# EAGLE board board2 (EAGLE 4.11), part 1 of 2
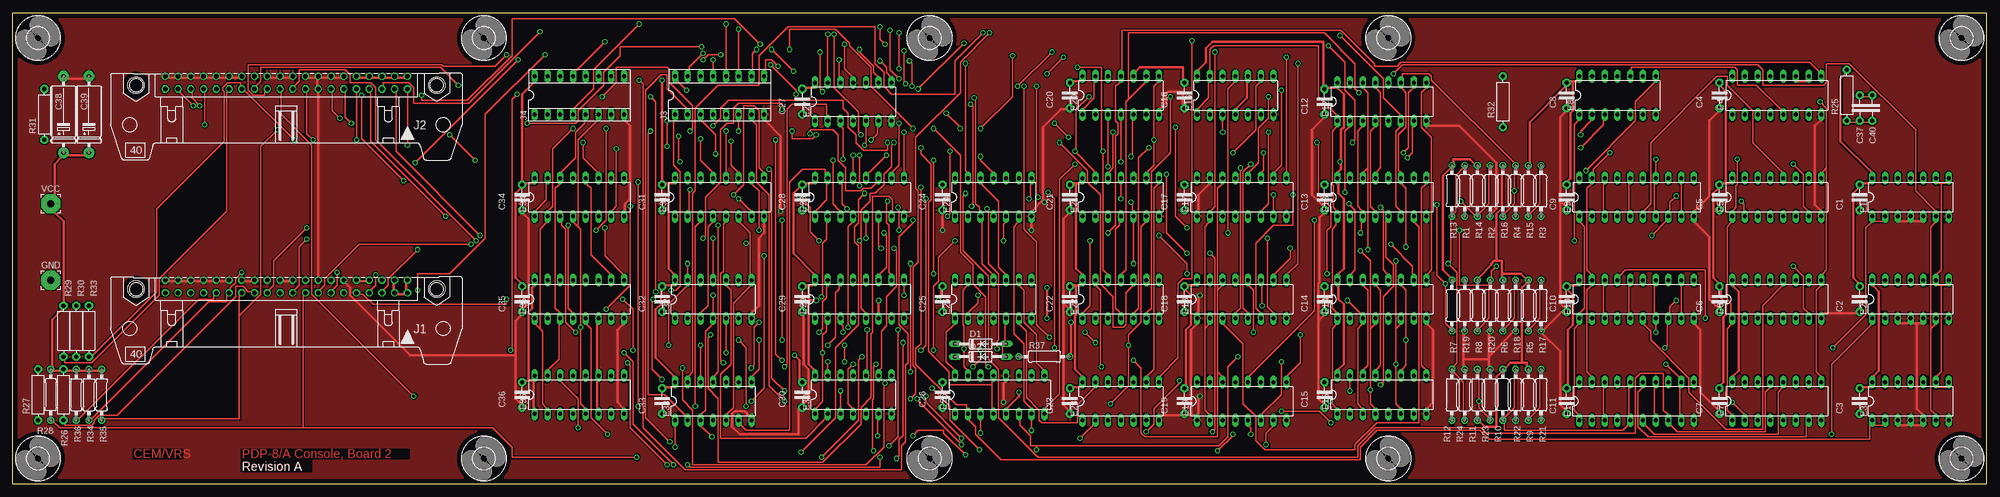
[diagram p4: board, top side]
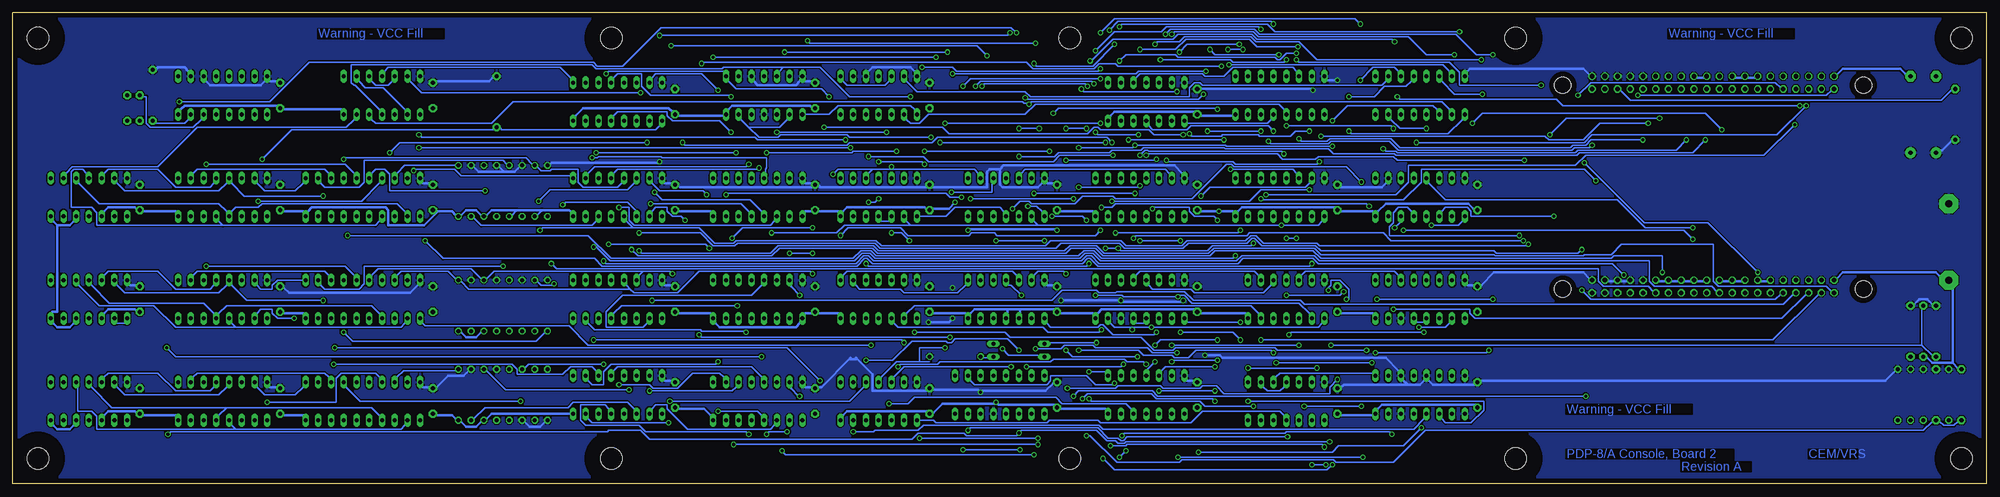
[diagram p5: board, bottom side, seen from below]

Size 393.7 x 93.98 mm. Coordinates in mm from the lower left corner, seen from the top.
Outline: 0,0 0,93.98 393.7,93.98 393.7,0 0,0
Copper layers (1*16): Top 0.035mm / dielectric 1.5mm / Bottom 0.035mm
Design rules "olimex8mil": minimum track width 10mil, minimum drill 24mil, track to track 8mil, track to pad 8mil, pad to pad 10mil, via to via 8mil, smd to smd 8mil, copper to edge 40mil, drill to drill 10mil, minimum pad ring 10mil, minimum via ring 8mil, stop-mask expansion 0mil, vias tented up to drill 0mil, thermal gap 10mil
Net classes: 1 Supply: width 0.508 mm

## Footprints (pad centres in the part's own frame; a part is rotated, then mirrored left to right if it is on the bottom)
C-5 = drill 0.813 pad 1.6 octagon: 1 -2.54,0; 2 2.54,0
E15-5 = drill 0.813 pad 2.159 round: + -7.62,0 | drill 0.813 pad 2.159 octagon: - 7.62,0
DO35-10 = drill 0.813 long: A 5.08,0; C -5.08,0
DIL14 = drill 0.813 long: 1 -7.62,-3.81; 2 -5.08,-3.81; 3 -2.54,-3.81; 4 0,-3.81; 5 2.54,-3.81; 6 5.08,-3.81; 7 7.62,-3.81; 8 7.62,3.81; 9 5.08,3.81; 10 2.54,3.81; 11 0,3.81; 12 -2.54,3.81; 13 -5.08,3.81; 14 -7.62,3.81
DIL16 = drill 0.813 long: 1 -8.89,-3.81; 2 -6.35,-3.81; 3 -3.81,-3.81; 4 -1.27,-3.81; 5 1.27,-3.81; 6 3.81,-3.81; 7 6.35,-3.81; 8 8.89,-3.81; 9 8.89,3.81; 10 6.35,3.81; 11 3.81,3.81; 12 1.27,3.81; 13 -1.27,3.81; 14 -3.81,3.81; 15 -6.35,3.81; 16 -8.89,3.81
DIL20 = drill 0.813 long: 1 -11.43,-3.81; 2 -8.89,-3.81; 3 -6.35,-3.81; 4 -3.81,-3.81; 5 -1.27,-3.81; 6 1.27,-3.81; 7 3.81,-3.81; 8 6.35,-3.81; 9 8.89,-3.81; 10 11.43,-3.81; 11 11.43,3.81; 12 8.89,3.81; 13 6.35,3.81; 14 3.81,3.81; 15 1.27,3.81; 16 -1.27,3.81; 17 -3.81,3.81; 18 -6.35,3.81; 19 -8.89,3.81; 20 -11.43,3.81
3,81/1,4 = drill 1.397 pad 3.81 octagon: 1 0,0
40H = drill 0.914 round: 1 -24.13,-1.27 | drill 0.914 octagon: 2 -24.13,1.27; 3 -21.59,-1.27; 4 -21.59,1.27; 5 -19.05,-1.27; 6 -19.05,1.27; 7 -16.51,-1.27; 8 -16.51,1.27; 9 -13.97,-1.27; 10 -13.97,1.27; 11 -11.43,-1.27; 12 -11.43,1.27; 13 -8.89,-1.27; 14 -8.89,1.27; 15 -6.35,-1.27; 16 -6.35,1.27; 17 -3.81,-1.27; 18 -3.81,1.27; 19 -1.27,-1.27; 20 -1.27,1.27; 21 1.27,-1.27; 22 1.27,1.27; 23 3.81,-1.27; 24 3.81,1.27; 25 6.35,-1.27; 26 6.35,1.27; 27 8.89,-1.27; 28 8.89,1.27; 29 11.43,-1.27; 30 11.43,1.27; 31 13.97,-1.27; 32 13.97,1.27; 33 16.51,-1.27; 34 16.51,1.27; 35 19.05,-1.27; 36 19.05,1.27; 37 21.59,-1.27; 38 21.59,1.27; 39 24.13,-1.27; 40 24.13,1.27 | hole 3.302: -29.972,0.533; 29.972,0.533
SOCKED-16 = drill 0.813 long: 1 -8.89,-3.81; 2 -6.35,-3.81; 3 -3.81,-3.81; 4 -1.27,-3.81; 5 1.27,-3.81; 6 3.81,-3.81; 7 6.35,-3.81; 8 8.89,-3.81; 9 8.89,3.81; 10 6.35,3.81; 11 3.81,3.81; 12 1.27,3.81; 13 -1.27,3.81; 14 -3.81,3.81; 15 -6.35,3.81; 16 -8.89,3.81
0207/10 = drill 0.813 octagon: 1 -5.08,0; 2 5.08,0
R-10 = drill 0.813 pad 1.6 octagon: 1 -5.08,0; 2 5.08,0
4,3 = hole 4.3: 0,0

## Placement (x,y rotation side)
C1  [C-5]  368.3,57.15 90 top
C2  [C-5]  368.3,36.83 90 top
C3  [C-5]  368.3,16.51 90 top
C4  [C-5]  340.36,77.47 90 top
C5  [C-5]  340.36,57.15 90 top
C6  [C-5]  340.36,36.83 90 top
C7  [C-5]  340.36,16.51 90 top
C8  [C-5]  309.88,77.47 90 top
C9  [C-5]  309.88,57.15 90 top
C10  [C-5]  309.88,36.83 90 top
C11  [C-5]  309.88,16.51 90 top
C12  [C-5]  261.62,76.2 90 top
C13  [C-5]  261.62,57.15 90 top
C14  [C-5]  261.62,36.83 90 top
C15  [C-5]  261.62,17.78 90 top
C16  [C-5]  233.68,77.47 90 top
C17  [C-5]  233.68,57.15 90 top
C18  [C-5]  233.68,36.83 90 top
C19  [C-5]  233.68,16.51 90 top
C20  [C-5]  210.82,77.47 90 top
C21  [C-5]  210.82,57.15 90 top
C22  [C-5]  210.82,36.83 90 top
C23  [C-5]  210.82,16.51 90 top
C24  [C-5]  185.42,57.15 90 top
C25  [C-5]  185.42,36.83 90 top
C26  [C-5]  185.42,17.78 90 top
C27  [C-5]  157.48,76.2 90 top
C28  [C-5]  157.48,57.15 90 top
C29  [C-5]  157.48,36.83 90 top
C30  [C-5]  157.48,17.78 90 top
C31  [C-5]  129.54,57.15 90 top
C32  [C-5]  129.54,36.83 90 top
C33  [C-5]  129.54,16.51 90 top
C34  [C-5]  101.6,57.15 90 top
C35  [C-5]  101.6,36.83 90 top
C36  [C-5]  101.6,17.78 90 top
C37  10  [C-5]  368.3,74.93 270 top
C38  6.8uf  [E15-5]  10.16,73.66 90 top
C39  6.8uf  [E15-5]  15.24,73.66 90 top
C40  47  [C-5]  370.84,74.93 270 top
D1  1N4148  [DO35-10]  193.04,27.94 0 top
D2  1N4148  [DO35-10]  193.04,25.4 0 top
E1  74LS95N  [DIL14]  378.46,57.15 0 top
E2  74LS95N  [DIL14]  378.46,36.83 0 top
E3  74LS95N  [DIL14]  378.46,16.51 0 top
E4  74LS123N  [DIL16]  351.79,77.47 0 top
E5  74LS175N  [DIL16]  351.79,57.15 0 top
E6  74LS175N  [DIL16]  351.79,36.83 0 top
E7  74LS175N  [DIL16]  351.79,16.51 0 top
E8  74LS00N  [DIL14]  320.04,77.47 0 top
E9  74S244N  [DIL20]  323.85,57.15 0 top
E10  74S244N  [DIL20]  323.85,36.83 0 top
E11  74S244N  [DIL20]  323.85,16.51 0 top
E12  74LS174N  [DIL16]  273.05,76.2 0 top
E13  74LS174N  [DIL16]  273.05,57.15 0 top
E14  74LS174N  [DIL16]  273.05,36.83 0 top
E15  74LS174N  [DIL16]  273.05,17.78 0 top
E16  74LS74N  [DIL14]  243.84,77.47 0 top
E17  74LS153N  [DIL16]  245.11,57.15 0 top
E18  74LS153N  [DIL16]  245.11,36.83 0 top
E19  74LS153N  [DIL16]  245.11,16.51 0 top
E20  74LS74N  [DIL14]  220.98,77.47 0 top
E21  74LS27N  [DIL14]  220.98,57.15 0 top
E22  74LS02N  [DIL14]  220.98,36.83 0 top
E23  7416N  [DIL14]  220.98,16.51 0 top
E24  74LS04N  [DIL14]  195.58,57.15 0 top
E25  74LS27N  [DIL14]  195.58,36.83 0 top
E26  74LS75N  [DIL16]  196.85,17.78 0 top
E27  7404N  [DIL14]  167.64,76.2 0 top
E28  74LS367N  [DIL16]  168.91,57.15 0 top
E29  74LS138N  [DIL16]  168.91,36.83 0 top
E30  74LS00N  [DIL14]  167.64,17.78 0 top
E31  74LS367N  [DIL16]  140.97,57.15 0 top
E32  74LS08N  [DIL14]  139.7,36.83 0 top
E33  74LS02N  [DIL14]  139.7,16.51 0 top
E34  74LS367N  [DIL16]  113.03,57.15 0 top
E35  74LS138N  [DIL16]  113.03,36.83 0 top
E36  74LS174N  [DIL16]  113.03,17.78 0 top
GND  [3,81/1,4]  7.62,40.64 0 top
J1  [40H]  54.61,39.37 180 top
J2  [40H]  54.61,80.01 180 top
J3  [SOCKED-16]  140.97,77.47 0 top
J4  [SOCKED-16]  113.03,77.47 0 top
R1  680  [0207/10]  289.56,58.42 90 top
R2  680  [0207/10]  294.64,58.42 90 top
R3  680  [0207/10]  304.8,58.42 90 top
R4  680  [0207/10]  299.72,58.42 90 top
R5  330  [0207/10]  302.26,35.56 90 top
R6  330  [0207/10]  297.18,35.56 90 top
R7  330  [0207/10]  287.02,35.56 90 top
R8  330  [0207/10]  292.1,35.56 90 top
R9  330  [0207/10]  302.26,17.78 90 top
R10  330  [0207/10]  297.18,17.78 90 top
R11  330  [0207/10]  292.1,17.78 270 top
R12  330  [0207/10]  287.02,17.78 270 top
R13  330  [0207/10]  287.02,58.42 90 top
R14  330  [0207/10]  292.1,58.42 90 top
R15  330  [0207/10]  302.26,58.42 90 top
R16  330  [0207/10]  297.18,58.42 90 top
R17  680  [0207/10]  304.8,35.56 90 top
R18  680  [0207/10]  299.72,35.56 90 top
R19  680  [0207/10]  289.56,35.56 90 top
R20  680  [0207/10]  294.64,35.56 90 top
R21  680  [0207/10]  304.8,17.78 90 top
R22  680  [0207/10]  299.72,17.78 90 top
R23  680  [0207/10]  294.64,17.78 270 top
R24  680  [0207/10]  289.56,17.78 270 top
R25  6K8  [R-10]  365.76,77.47 90 top
R26  180  [R-10]  10.16,17.78 270 top
R27  390  [R-10]  5.08,17.78 90 top
R28  1K  [0207/10]  7.62,17.78 90 top
R29  180  [R-10]  10.16,30.48 270 top
R30  390  [R-10]  12.7,30.48 270 top
R31  1K  [R-10]  6.35,73.66 90 top
R32  1K  [R-10]  297.18,76.2 270 top
R33  1K  [R-10]  15.24,30.48 270 top
R34  1K  [0207/10]  15.24,17.78 270 top
R35  1K  [0207/10]  17.78,17.78 270 top
R36  1K  [0207/10]  12.7,17.78 270 top
R37  10K  [0207/10]  205.74,25.4 0 top
U$11  [4,3]  93.98,88.9 0 top
U$12  [4,3]  5.08,88.9 0 top
U$13  [4,3]  182.88,88.9 0 top
U$14  [4,3]  274.32,88.9 0 top
U$15  [4,3]  388.62,88.9 0 top
U$16  [4,3]  388.62,5.08 0 top
U$17  [4,3]  274.32,5.08 0 top
U$18  [4,3]  182.88,5.08 0 top
U$19  [4,3]  93.98,5.08 0 top
U$20  [4,3]  5.08,5.08 0 top
VCC  [3,81/1,4]  7.62,55.88 0 top

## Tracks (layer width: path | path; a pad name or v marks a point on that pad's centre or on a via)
ADDR0  (via drill 0.61)
  Top 0.254: v256.29,83.82 256.29,43.94 254.25,41.91 E18.9 | v152.65,83.31 151.38,84.58 150.11,84.58 150.11,82.55 J3.9
  Bottom 0.254: v256.29,83.82 256.03,84.07 191.52,84.07 190.25,82.8 178.05,82.8 177.04,83.82 173.74,83.82 173.23,83.31 v152.65,83.31
ADDR1  (via drill 0.61)
  Top 0.254: v251.46,57.66 251.46,54.61 E17.7 | v204.47,57.15 204.22,57.4 v204.22,79.25 | v176.78,80.77 175.01,82.55 v175.01,90.42 | v142.24,91.69 142.24,82.55 J3.12
  Bottom 0.254: v251.46,57.66 251.21,57.91 207.52,57.91 206.76,57.15 v204.47,57.15 | v204.22,79.25 202.69,80.77 v176.78,80.77 | v175.01,90.42 173.23,92.2 142.75,92.2 v142.24,91.69
ADDR2  (via drill 0.61)
  Top 0.254: v254,85.09 254,62.23 E17.9 | v206.25,81.79 v209.55,85.09 | v155.7,82.3 v151.38,86.61 | v148.34,86.61 147.57,85.85 147.57,82.55 J3.10
  Bottom 0.254: v209.55,85.09 v254,85.09 | v206.25,81.79 169.67,81.79 169.16,82.3 v155.7,82.3 | v151.38,86.61 v148.34,86.61
ADRLTH\
  Top 0.254: E14.9 282.19,41.91 282.96,42.67 282.96,69.09 280.92,71.12 280.92,77.98 281.69,78.74 E12.9
  Bottom 0.254: E8.11 319.53,82.3 318.77,83.06 284.48,83.06 282.45,81.03 E12.9
BEMA0
  Bottom 0.254: E27.10 169.67,81.03 168.91,81.79 156.46,81.79 155.96,81.28 152.15,81.28 150.37,83.06 138.43,83.06 137.67,82.3 J3.14
BEMA1  (via drill 0.61)
  Top 0.254: v172.97,84.33 174.24,83.06 174.24,82.04 175.01,81.28 E27.8 | v137.67,85.85 134.87,83.06 134.87,82.55 J3.15
  Bottom 0.254: v172.97,84.33 171.7,85.6 161.8,85.6 161.29,85.09 141.99,85.09 141.48,84.58 140.97,84.58 139.7,85.85 v137.67,85.85
BEMA2  (via drill 0.61)
  Top 0.254: v139.7,84.58 139.7,82.55 J3.13 | v164.85,84.58 164.85,81.28 E27.12
  Bottom 0.254: v139.7,84.58 140.21,84.07 150.37,84.07 150.88,84.58 v164.85,84.58
BFSW\  (via drill 0.61)
  Top 0.254: v177.8,70.1 177.8,62.23 E28.9 | v169.16,69.6 168.66,70.1 168.66,74.17 163.83,78.99 v163.83,89.66 | v98.55,85.6 96.27,83.31 85.85,83.31 85.6,83.57 46.99,83.57 46.99,78.49 48.01,77.47 50.29,77.47 50.29,78.49 J2.24
  Bottom 0.254: v177.8,70.1 177.29,69.6 v169.16,69.6 | v163.83,89.66 162.81,90.68 146.05,90.68 145.03,89.66 105.92,89.66 101.85,85.6 v98.55,85.6
BKDTACNTL\  (via drill 0.61)
  Top 0.254: v163.58,64.52 163.58,55.88 164.85,54.61 E28.3 | v133.1,64.26 132.84,64.52 v132.84,69.34 | v67.56,71.88 66.29,73.15 66.29,78.23 J2.12
  Bottom 0.254: v163.58,64.52 163.32,64.26 150.37,64.26 149.86,63.75 133.6,63.75 v133.1,64.26 | v132.84,69.34 88.14,69.34 87.38,68.58 80.52,68.58 77.22,71.88 v67.56,71.88
BOOTF\  (via drill 0.61)
  Top 0.254: v176.78,71.88 176.78,63.5 175.51,62.23 E28.10 | v210.57,69.09 v207.77,71.88
  Bottom 0.254: v207.77,71.88 v176.78,71.88 | v210.57,69.09 226.82,69.09 227.33,69.6 240.54,69.6 241.05,69.09 244.86,69.09 246.89,71.12 | 246.89,71.12 248.41,72.64 E16.6 | 246.89,71.12 240.79,71.12 239.27,72.64 E16.2
BPOK  (via drill 0.61)
  Top 0.254: E16.1 236.47,74.93 238.51,76.96 238.51,80.01 E16.13 238.76,82.55 238.76,86.61 239.52,87.38 260.35,87.38 260.35,77.22 263.91,73.66 E12.1 263.91,71.12 263.14,70.36 263.14,59.69 263.4,59.44 263.4,55.12 263.91,54.61 E13.1 263.91,52.07 263.91,51.56 263.14,50.8 263.14,35.05 263.91,34.29 E14.1 263.91,31.75 263.14,30.99 263.14,16.51 | E20.1 213.61,74.93 215.65,76.96 215.65,80.01 E20.13 | 263.14,16.51 263.14,16 263.91,15.24 E15.1 | 263.14,16.51 v262.64,16.51 | E7.1 342.65,13.97 341.88,14.73 341.88,30.99 342.65,31.75 E6.1 342.65,34.29 342.65,36.07 341.88,36.83 341.88,51.31 342.65,52.07 E5.1 343.15,54.61 343.66,55.12 343.66,59.44 343.92,59.69 v343.92,64.77
  Bottom 0.254: J4.10 119.89,80.26 120.65,79.5 156.46,79.5 156.97,80.01 157.99,80.01 159,78.99 159,77.22 190.75,77.22 191.77,78.23 213.36,78.23 215.39,80.26 E20.13 | E16.1 235.71,73.66 230.89,73.66 229.11,75.44 214.63,75.44 213.87,74.68 E20.1 | v262.64,16.51 226.82,16.51 224.03,19.3 E23.10 | E12.1 264.67,71.37 265.43,70.61 296.16,70.61 296.42,70.87 R32.2 297.69,70.61 338.07,70.61 v343.92,64.77
BRUN  (via drill 0.61)
  Top 0.254: E24.6 200.41,52.07 199.64,51.31 199.64,29.97 201.68,27.94 201.68,16.51 202.95,15.24 E26.7 203.2,12.7 v203.2,10.67 | v127.25,77.22 128.27,76.2 v128.27,38.35 | v139.7,37.59 139.7,34.29 E32.4 139.45,31.75 138.18,30.48 138.18,14.73 137.41,13.97 E33.3 137.41,11.43 v139.45,9.4
  Bottom 0.254: v127.25,77.22 122.17,77.22 120.14,79.25 115.82,79.25 114.81,80.26 J4.12 | v128.27,38.35 129.03,37.59 v139.7,37.59 | v203.2,10.67 202.69,11.18 177.29,11.18 175.26,9.14 173.23,9.14 172.72,8.64 172.21,8.64 171.45,9.4 v139.45,9.4
BUS0  (via drill 0.61)
  Top 0.254: E11.3 317.25,13.97 317.25,19.05 E11.18 | R9.1 302.51,13.21 304.55,15.24 304.55,22.35 R21.2 | E15.3 268.99,15.24 268.22,16 268.22,30.99 268.99,31.75 E14.3 268.73,34.04 v266.19,36.58
  Bottom 0.254: E11.18 316.99,21.34 315.72,22.61 305.31,22.61 R21.2 | v266.19,36.58 186.44,36.58 184.4,38.61 177.55,38.61 177.04,38.1 173.74,38.1 173.48,38.35 160.02,38.35 158.24,36.58 136.91,36.58 136.14,35.81 40.64,35.81 38.61,37.85 J1.34 | R9.1 301.75,12.95 299.47,15.24 282.96,15.24 281.94,16.26 271.02,16.26 269.75,14.99 E15.3
BUS1  (via drill 0.61)
  Top 0.254: E10.3 317.25,34.29 317.25,39.37 E10.18 | R5.1 302.51,30.99 304.55,33.02 304.55,40.13 R17.2 | E15.13 272.03,22.86 272.8,23.62 272.8,38.61 272.03,39.37 E14.13 | v118.36,34.8 123.19,39.62 v123.19,55.37 | v176.53,55.12 176.78,54.86 v176.78,50.55 | v228.6,49.53 234.19,43.94 v234.19,41.91
  Bottom 0.254: E10.18 316.99,41.66 316.23,42.42 306.83,42.42 305.31,40.89 R17.2 304.29,40.39 302.77,38.86 270.51,38.86 | v118.36,34.8 103.12,34.8 103.12,34.04 102.11,33.02 40.89,33.02 36.07,37.85 J1.36 | v123.19,55.37 123.7,55.88 173.74,55.88 174.5,55.12 v176.53,55.12 | v176.78,50.55 177.8,49.53 197.36,49.53 197.87,50.04 202.44,50.04 202.95,49.53 215.14,49.53 216.66,51.05 227.08,51.05 v228.6,49.53 | v234.19,41.91 234.7,42.42 256.79,42.42 261.11,38.1 269.75,38.1 270.51,38.86 | 270.51,38.86 271.27,39.62 E14.13
BUS2  (via drill 0.61)
  Top 0.254: E9.3 317.25,54.61 317.25,59.69 E9.18 | R15.1 302.51,53.85 304.55,55.88 304.55,62.99 R3.2 | E13.6 276.61,54.61 275.84,55.37 275.84,70.36 276.61,71.12 E12.6 276.61,73.66 273.3,76.96 273.3,80.77 v264.67,89.41 | v144.78,28.7 146.3,27.18 v146.3,15.49 | v179.07,17.02 180.09,18.03 180.09,23.11 179.58,23.62 179.58,43.18 180.59,44.2 180.59,58.42 180.09,58.93 180.09,69.09 188.98,77.98 188.98,84.07 v194.82,89.92
  Bottom 0.254: E9.18 316.99,61.98 315.47,63.5 305.31,63.5 R3.2 | v144.78,28.7 42.67,28.7 33.53,37.85 J1.38 | v146.3,15.49 155.96,15.49 156.97,16.51 178.56,16.51 v179.07,17.02 | v194.82,89.92 195.33,89.41 v264.67,89.41 | R15.1 301.75,53.09 300.23,51.56 278.13,51.56 277.37,52.32 E13.6
BUS3  (via drill 0.61)
  Top 0.254: E11.16 322.33,19.05 322.33,13.97 E11.5 322.07,11.68 321.06,10.67 297.43,10.67 297.43,12.19 R10.1 297.43,13.21 299.47,15.24 299.47,22.35 R22.2 | 270.76,30.99 v270.76,18.8 270.76,16 271.53,15.24 E15.4 | 270.76,30.99 271.53,31.75 E14.4 | v268.73,46.48 270.76,44.45 270.76,30.99
  Bottom 0.254: v268.73,46.48 268.22,45.97 242.57,45.97 241.05,47.5 222,47.5 220.98,46.48 183.9,46.48 182.88,47.5 177.55,47.5 176.02,45.97 155.19,45.97 154.18,46.99 134.11,46.99 132.84,45.72 98.3,45.72 98.04,45.47 80.52,45.47 80.26,45.72 74.93,45.72 72.9,47.75 54.61,47.75 54.61,40.39 53.59,39.37 32,39.37 30.99,38.35 J1.40 | v270.76,18.8 295.4,18.8 299.21,22.61 R22.2
BUS4  (via drill 0.61)
  Top 0.254: E10.5 322.33,34.29 322.33,39.37 E10.16 | R6.1 297.43,30.99 299.47,33.02 299.47,40.13 R18.2 | E15.14 269.49,22.86 270.26,23.62 270.26,38.61 269.49,39.37 E14.14 | v58.67,48.77 57.15,47.24 57.15,39.62 56.13,38.61 J1.20 | v116.33,50.55 118.36,52.58 v118.36,70.87 | v139.7,71.37 141.22,72.9 141.22,74.93 142.75,76.45 165.61,76.45 165.61,74.93 166.62,73.91 166.62,71.12 168.15,69.6 168.15,68.07 169.67,66.55 174.5,66.55 v174.5,68.07 | v260.1,68.07 260.35,67.82 260.35,57.66 262.89,55.12 262.89,51.31 262.13,50.55 v262.13,41.91
  Bottom 0.254: E10.16 322.07,41.66 320.8,42.93 302.26,42.93 300.23,40.89 R18.2 299.21,40.89 297.69,42.42 267.97,42.42 | v58.67,48.77 60.45,50.55 v116.33,50.55 | v118.36,70.87 118.87,71.37 v139.7,71.37 | v174.5,68.07 175.51,69.09 209.3,69.09 210.31,68.07 226.82,68.07 227.33,67.56 259.59,67.56 v260.1,68.07 | v262.13,41.91 262.64,42.42 267.97,42.42 | 267.97,42.42 268.73,41.66 E14.14
BUS5  (via drill 0.61)
  Top 0.254: E9.5 322.33,54.61 322.33,59.69 E9.16 | R16.1 297.43,53.85 299.47,55.88 v299.47,58.42 299.47,62.99 R4.2 299.47,64.01 282.96,80.52 282.96,81.28 282.45,81.79 277.11,81.79 277.11,81.28 E12.11 277.11,78.74 277.88,77.98 277.88,71.12 276.35,69.6 276.35,62.48 276.61,62.23 E13.11 277.11,59.69 277.88,58.93 v277.88,47.24
  Bottom 0.254: v299.47,58.42 318.52,58.42 318.52,61.72 319.53,62.74 321.31,62.74 322.07,61.98 E9.16 | v277.88,47.24 277.37,47.24 274.57,44.45 225.81,44.45 224.28,45.97 222.76,45.97 221.74,44.96 180.85,44.96 179.83,45.97 178.31,45.97 176.78,44.45 149.61,44.45 148.59,45.47 134.11,45.47 133.1,44.45 67.31,44.45 67.31,40.39 66.29,39.37 54.86,39.37 53.85,38.35 J1.22
BUS6  (via drill 0.61)
  Top 0.254: E11.7 327.41,13.97 327.41,19.05 E11.14 | R23.2 294.39,13.21 292.35,15.24 v292.35,16.51 292.35,22.35 R11.1 | 275.84,30.99 v275.84,23.88 275.84,16 276.61,15.24 E15.6 | 275.84,30.99 276.61,31.75 E14.6 | v72.39,41.66 72.39,39.62 71.37,38.61 J1.8 | v275.84,44.45 275.84,30.99
  Bottom 0.254: v292.35,16.51 324.36,16.51 327.15,19.3 E11.14 | v72.39,41.66 74.68,43.94 133.35,43.94 134.37,44.96 148.34,44.96 149.35,43.94 177.04,43.94 178.56,45.47 179.58,45.47 180.59,44.45 222,44.45 223.01,45.47 224.03,45.47 225.55,43.94 275.34,43.94 v275.84,44.45 | v275.84,23.88 290.83,23.88 291.59,23.11 R11.1
BUS7  (via drill 0.61)
  Top 0.254: E10.14 327.41,39.37 327.41,34.29 E10.7 327.66,31.75 v327.66,30.23 | R7.1 286.77,30.99 285.75,32 v285.75,39.88 285.5,40.13 283.97,41.66 v283.97,55.63 | E12.3 268.99,71.12 268.22,70.36 268.22,55.37 268.99,54.61 E13.3 268.99,52.07 268.99,50.29 v268.73,50.04 | v80.77,46.74 74.93,40.89 74.93,39.62 73.91,38.61 J1.6
  Bottom 0.254: v285.75,39.88 286,39.62 288.29,39.62 289.05,40.39 R19.2 | v327.66,30.23 325.88,28.45 289.31,28.45 287.53,30.23 R7.1 | v80.77,46.74 81.53,45.97 97.79,45.97 98.3,46.48 132.84,46.48 133.86,47.5 144.53,47.5 146.05,49.02 146.56,49.02 147.57,48.01 159.26,48.01 160.27,46.99 171.96,46.99 172.97,48.01 184.66,48.01 185.67,46.99 220.73,46.99 221.74,48.01 249.17,48.01 249.68,47.5 254,47.5 256.54,50.04 v268.73,50.04 | v283.97,55.63 283.46,56.13 271.02,56.13 269.49,54.61 E13.3
BUS8  (via drill 0.61)
  Top 0.254: E13.13 272.03,62.23 272.8,62.99 272.8,77.98 272.03,78.74 E12.13 | R24.2 289.31,13.21 289.31,20.32 287.27,22.35 R12.1 287.27,23.37 288.04,24.13 288.04,42.16 286.51,43.69 v286.26,43.94 286.77,44.45 286.77,52.83 R13.1 287.27,53.85 287.78,54.36 287.78,61.47 289.31,62.99 R1.2 | E9.7 327.41,54.61 327.41,59.69 E9.14 327.66,62.23 v327.66,64.77
  Bottom 0.254: v286.26,43.94 285.24,42.93 77.47,42.93 77.47,40.39 76.45,39.37 67.56,39.37 66.55,38.35 J1.12 | v327.66,64.77 327.41,65.02 291.34,65.02 290.07,63.75 R1.2 289.05,63.25 288.29,62.48 286.51,62.48 286.26,62.74 280.92,62.74 280.92,60.2 279.91,59.18 273.05,59.18 272.29,59.94 E13.13
BUS9  (via drill 0.61)
  Top 0.254: E11.9 332.49,13.97 332.49,19.05 E11.12 332.23,21.34 v329.69,23.88 | E14.11 277.11,39.37 277.88,38.61 v277.88,28.7 277.88,23.62 277.11,22.86 E15.11 | v98.55,36.83 98.55,35.81 71.88,35.81 69.85,37.85 69.09,37.85 J1.10 | v121.67,36.83 123.7,34.8 v123.7,26.67 | v215.9,28.19 v213.87,30.23
  Bottom 0.254: v329.69,23.88 294.13,23.88 293.12,22.86 293.12,21.84 283.97,21.84 282.45,23.37 278.13,23.37 277.37,22.61 E15.11 | v121.67,36.83 v98.55,36.83 | v123.7,26.67 141.48,26.67 141.99,27.18 161.8,27.18 162.31,26.67 166.12,26.67 168.66,29.21 194.82,29.21 195.83,30.23 v213.87,30.23 | v215.9,28.19 216.41,28.7 v277.88,28.7
BUS10  (via drill 0.61)
  Top 0.254: E10.9 332.74,34.29 332.74,39.37 E10.12 | 294.39,39.62 294.39,40.13 R20.2 294.89,41.15 294.89,42.42 v295.91,43.43 | 294.39,39.62 294.39,33.02 292.35,30.99 R8.1 | E13.4 271.53,54.61 270.76,55.37 270.76,70.36 271.53,71.12 E12.4 | v91.44,47.75 69.09,47.75 62.23,40.89 62.23,39.62 61.21,38.61 J1.16 | 294.39,39.62 288.54,39.62 v288.54,50.55
  Bottom 0.254: v295.91,43.43 323.6,43.43 323.6,39.88 324.61,38.86 331.47,38.86 332.23,39.62 E10.12 | v91.44,47.75 91.69,47.5 133.1,47.5 133.6,48.01 144.27,48.01 145.8,49.53 146.81,49.53 147.83,48.51 159.51,48.51 160.53,47.5 171.7,47.5 172.72,48.51 186.69,48.51 187.71,47.5 220.47,47.5 221.49,48.51 249.43,48.51 249.94,48.01 253.75,48.01 256.79,51.05 270,51.05 | 270,51.05 271.27,52.32 E13.4 | v288.54,50.55 288.04,51.05 270,51.05
BUS11  (via drill 0.61)
  Top 0.254: E9.9 332.74,54.61 332.74,59.69 E9.12 | R2.2 294.39,62.99 294.39,55.88 292.35,53.85 R14.1 291.59,53.59 v288.8,56.39 | 270.26,62.99 269.49,62.23 E13.14 | 270.26,62.99 270.26,77.98 269.49,78.74 E12.14 | v64.77,42.16 64.77,39.62 63.75,38.61 J1.14 | v270.26,46.74 270.26,62.99
  Bottom 0.254: E9.12 332.23,59.94 331.47,59.18 324.61,59.18 323.6,60.2 323.6,64.52 295.91,64.52 295.15,63.75 R2.2 | v64.77,42.16 64.77,45.47 74.42,45.47 74.93,44.96 132.84,44.96 134.37,46.48 153.92,46.48 154.94,45.47 176.28,45.47 177.8,46.99 182.63,46.99 183.64,45.97 221.23,45.97 222.25,46.99 240.79,46.99 242.32,45.47 268.99,45.47 v270.26,46.74 | v288.8,56.39 286.51,58.67 271.02,58.67 269.75,59.94 E13.14
BUSEN\  (via drill 0.61)
  Top 0.254: v58.67,51.05 52.07,44.45 52.07,39.62 51.05,38.61 J1.24
  Bottom 0.254: v58.67,51.05 68.07,51.05 73.66,56.64 107.95,56.64 111.25,59.94 E34.13
DEP\  (via drill 0.61)
  Top 0.254: v170.18,49.02 170.18,52.07 E28.5 | v92.46,48.51 72.39,68.58 72.39,78.99 71.37,80.01 67.31,80.01 67.31,81.53 66.29,82.55 57.15,82.55 57.15,80.26 56.13,79.25 J2.20
  Bottom 0.254: v170.18,49.02 169.67,49.53 147.57,49.53 147.07,50.04 120.4,50.04 118.87,48.51 v92.46,48.51
DISP0
  Top 0.254: E36.15 106.93,22.86 108.97,24.89 108.97,31.75 E35.3 108.97,34.29 108.2,35.05 108.2,58.93 108.97,59.69 E34.14 109.47,62.23 112.27,65.02 112.27,70.1 114.05,71.88 114.05,72.39 J4.5
DISP1  (via drill 0.61)
  Top 0.254: 112.78,51.31 112.01,52.07 E34.4 | 112.78,51.31 113.28,50.8 v113.28,31.24 113.28,16 114.05,15.24 E36.5 | 112.78,51.31 112.78,68.58 116.59,72.39 J4.6
  Bottom 0.254: v113.28,31.24 107.95,31.24 107.19,32 E35.2
DISP2  (via drill 0.61)
  Top 0.254: 105.16,30.99 105.66,30.48 105.66,16 106.43,15.24 E36.2 | 105.16,30.99 104.39,31.75 E35.1 | 105.16,30.99 105.16,50.8 106.43,52.07 E34.2 106.93,54.61 107.7,55.37 107.7,66.8 v111.76,70.87
  Bottom 0.254: v111.76,70.87 117.09,70.87 118.87,72.64 J4.7
DISPINH  (via drill 0.61)
  Top 0.254: v243.33,66.04 247.9,70.61 247.9,79.25 248.67,80.01 E16.9 | E22.12 218.19,41.91 217.42,42.67 v217.42,66.29 217.17,66.55 217.17,83.06 v212.34,83.06 | v124.97,91.69 115.82,82.55 115.82,78.74 112.01,74.93 J4.4 | v176.78,82.8 v176.78,89.92
  Bottom 0.254: v217.42,66.29 226.06,66.29 226.31,66.04 v243.33,66.04 | v124.97,91.69 125.98,92.71 173.99,92.71 v176.78,89.92 | v176.78,82.8 177.29,82.3 205.49,82.3 206.25,83.06 v212.34,83.06
DISPLAY0  (via drill 0.61)
  Top 0.254: v249.94,7.87 249.94,10.16 251.21,11.43 E19.7 | v189.23,7.87 180.34,16.76 v180.34,17.02 | v153.92,16.51 150.88,19.56 150.88,57.66 148.34,60.2 148.34,71.63 147.57,72.39 J3.7
  Bottom 0.254: v249.94,7.87 v189.23,7.87 | v180.34,17.02 179.32,18.03 166.62,18.03 165.61,17.02 154.43,17.02 v153.92,16.51
DISPLAY1  (via drill 0.61)
  Top 0.254: v256.79,29.72 256.79,24.13 254.25,21.59 E19.9 | v206.76,29.21 204.22,31.75 204.22,48.26 201.68,50.8 v201.68,79.25 | v178.05,79.76 177.8,80.01 v177.8,86.36 | v144.78,90.68 144.78,82.55 J3.11
  Bottom 0.254: v256.79,29.72 256.29,29.21 v206.76,29.21 | v201.68,79.25 200.66,80.26 178.56,80.26 v178.05,79.76 | v177.8,86.36 173.99,90.17 164.59,90.17 163.58,91.19 145.29,91.19 v144.78,90.68
DISPLAY2  (via drill 0.61)
  Top 0.254: v250.19,49.02 250.19,35.31 251.21,34.29 E18.7 | v234.19,51.05 231.9,53.34 v231.9,71.12 | v160.27,69.6 159.51,68.83 155.45,68.83 v155.45,70.36 | v144.78,70.36 144.78,72.39 J3.6
  Bottom 0.254: v250.19,49.02 248.16,51.05 v234.19,51.05 | v231.9,71.12 208.28,71.12 207.01,69.85 179.32,69.85 178.05,71.12 177.29,71.12 176.78,70.61 167.13,70.61 166.12,69.6 v160.27,69.6 | v155.45,70.36 v144.78,70.36
DSPLTH\  (via drill 0.61)
  Top 0.254: E15.9 281.69,22.86 280.92,23.62 280.92,58.93 281.69,59.69 E13.9 | v313.69,62.48 323.6,72.39 323.6,76.2 327.41,80.01 E8.8
  Bottom 0.254: v313.69,62.48 313.44,62.74 305.56,62.74 304.29,61.47 282.45,61.47 E13.9
E30PIN8  (via drill 0.61)
  Top 0.254: v179.07,43.94 v179.07,22.35 | v223.52,43.94 223.52,52.07 E21.5 223.27,54.61 223.27,55.88 v223.01,56.13 | v220.98,56.9 220.98,59.69 E21.11
  Bottom 0.254: v179.07,22.35 175.77,22.35 E30.8 | v179.07,43.94 179.58,43.43 223.01,43.43 v223.52,43.94 | v220.98,56.9 221.74,56.13 v223.01,56.13
E35-Y4
  Bottom 0.254: E35.11 117.35,41.66 118.11,42.42 135.89,42.42 136.65,41.66 E32.12
EMA0\  (via drill 0.61)
  Top 0.254: R34.2 15.75,12.95 39.12,36.32 42.67,36.32 42.67,37.85 J1.30 43.43,38.61 43.43,39.12 44.45,40.13 44.45,40.89 v45.72,42.16 | v165.86,87.63 165.86,82.8 167.39,81.28 E27.11 | v80.26,64.01 v100.84,84.58
  Bottom 0.254: v165.86,87.63 165.35,88.14 161.04,88.14 160.02,89.15 146.81,89.15 145.8,88.14 137.16,88.14 133.6,84.58 v100.84,84.58 | v80.26,64.01 68.33,52.07 55.63,52.07 v45.72,42.16
EMA1\  (via drill 0.61)
  Top 0.254: 45.21,33.53 45.21,37.85 J1.28 | 45.21,33.53 45.21,12.95 18.29,12.95 R35.2 | v168.91,86.61 168.91,86.11 171.7,83.31 171.7,82.04 172.47,81.28 E27.9 | v137.41,87.12 121.16,87.12 121.16,85.34 117.86,82.04 117.86,79.5 112.78,74.42 112.78,72.39 112.27,71.88 v102.62,71.88 | v52.83,70.61 49.53,67.31 49.53,37.85 45.21,33.53
  Bottom 0.254: v168.91,86.61 161.8,86.61 159.77,88.65 147.07,88.65 145.54,87.12 v137.41,87.12 | v102.62,71.88 100.58,73.91 56.13,73.91 v52.83,70.61
EMA2\  (via drill 0.61)
  Top 0.254: R36.2 13.21,12.95 37.08,36.83 40.13,36.83 40.13,37.85 J1.32 | v162.56,89.66 162.56,81.28 E27.13 | v106.17,85.6 94.23,73.66 94.23,49.02 87.12,41.91 80.77,41.91 v80.77,38.61
  Bottom 0.254: v162.56,89.66 162.05,90.17 146.3,90.17 145.29,89.15 115.32,89.15 111.76,85.6 v106.17,85.6 | v80.77,38.61 78.99,36.83 42.16,36.83 41.15,37.85 J1.32
EMODE\  (via drill 0.61)
  Top 0.254: 382.52,30.99 382.52,14.73 383.29,13.97 E3.6 | 382.52,30.99 383.29,31.75 E2.6 | 382.52,30.99 382.52,51.31 383.29,52.07 E1.6 383.29,54.61 379.48,58.42 379.48,70.61 366.27,83.82 361.7,83.82 361.7,80.01 361.19,79.5 349,79.5 349,82.55 347.98,83.57 277.11,83.57 v275.34,81.79 | v230.89,77.22 230.89,66.04 227.08,62.23 227.08,35.05 226.31,34.29 E22.6
  Bottom 0.254: v230.89,77.22 232.41,78.74 249.43,78.74 250.95,80.26 E16.8 251.97,82.3 274.83,82.3 v275.34,81.79
ENT0  (via drill 0.61)
  Top 0.254: E7.13 350.27,19.05 349.5,18.29 349.5,10.41 331.98,10.41 330.71,11.68 E11.8 329.95,13.97 329.18,14.73 329.18,22.1 324.61,22.1 323.6,21.08 323.6,10.16 293.88,10.16 292.86,11.18 271.78,11.18 268.22,7.62 268.22,5.33 204.47,5.33 196.6,13.21 196.6,22.86 194.56,24.89 194.56,41.4 189.48,46.48 189.48,57.4 v189.99,57.91 | v112.78,11.18 112.78,17.02 109.47,20.32 E36.14 | v157.23,6.35 164.08,13.21 164.08,27.18 168.66,31.75 168.66,47.5 167.89,48.26 167.89,51.31 168.66,52.07 168.66,56.64 v169.93,57.91
  Bottom 0.254: E3.13 372.87,19.3 371.35,17.78 352.55,17.78 351.03,19.3 E7.13 | v112.78,11.18 116.33,7.62 129.29,7.62 130.56,6.35 v157.23,6.35 | v189.99,57.91 v169.93,57.91
ENT1  (via drill 0.61)
  Top 0.254: v226.06,10.41 227.58,11.94 227.58,14.99 232.66,20.07 v232.66,20.57 | v329.44,27.18 329.95,27.69 329.95,31.75 E10.8 330.45,34.29 330.45,35.31 v331.72,36.58
  Bottom 0.254: E2.13 372.87,39.62 371.35,38.1 352.55,38.1 351.03,39.62 E6.13 350.01,39.62 346.96,36.58 v331.72,36.58 | v226.06,10.41 222,10.41 221.74,10.67 213.11,10.67 212.09,11.68 177.04,11.68 176.28,10.92 114.3,10.92 112.27,12.95 E36.4 | v232.66,20.57 239.27,27.18 v329.44,27.18
ENT2  (via drill 0.61)
  Top 0.254: v147.32,16.51 149.86,19.05 v149.86,45.47 | v326.9,49.53 329.69,52.32 E9.8 330.45,54.61 330.45,56.13 v331.72,57.4
  Bottom 0.254: E1.13 372.87,59.94 371.35,58.42 352.55,58.42 351.03,59.94 E5.13 350.01,59.94 347.47,57.4 v331.72,57.4 | v147.32,16.51 100.33,16.51 100.33,14.73 102.87,12.19 107.95,12.19 108.71,12.95 E36.3 | v149.86,45.47 150.37,44.96 176.53,44.96 178.05,46.48 180.09,46.48 181.1,45.47 221.49,45.47 222.5,46.48 224.54,46.48 226.06,44.96 274.32,44.96 278.89,49.53 v326.9,49.53
FUN\  (via drill 0.61)
  Top 0.254: v192.53,37.59 192.53,36.07 190.75,34.29 E25.2 | v151.13,83.57 156.21,78.49 v156.21,77.72 | v191.77,76.96 192.02,76.71 192.02,55.88 192.79,55.12 192.79,54.61 E24.3 193.29,52.07 193.29,43.94 195.33,41.91 E25.11
  Bottom 0.254: v192.53,37.59 194.56,39.62 195.07,39.62 E25.11 | v151.13,83.57 108.46,83.57 107.19,82.3 J4.15 | v156.21,77.72 157.23,76.71 191.52,76.71 v191.77,76.96
GATEENT\  (via drill 0.61)
  Top 0.254: E11.1 312.17,13.97 311.4,14.73 311.4,30.99 312.17,31.75 E10.1 312.67,34.29 313.44,35.05 313.44,51.31 312.67,52.07 E9.1 | v218.95,16 222.5,19.56 v222.5,27.69 222.5,29.72 225.04,32.26 225.04,51.31 225.81,52.07 E21.6
  Bottom 0.254: v218.95,16 215.14,16 213.87,17.27 185.67,17.27 184.4,16 171.7,16 170.69,14.99 E30.5 | v222.5,27.69 278.89,27.69 282.7,31.5 311.4,31.5 311.91,32 E10.1
GATESR\  (via drill 0.61)
  Top 0.254: E11.19 314.71,21.59 313.94,22.35 313.94,38.61 314.71,39.37 E10.19 314.71,41.91 313.94,42.67 313.94,58.93 314.71,59.69 E9.19 315.21,62.23 315.21,62.74 v318.52,66.04 | v139.7,49.02 139.7,41.91 E32.11 | v137.67,49.02 138.18,49.53 138.18,57.15 141.22,60.2 141.22,70.61 142.49,71.88 143.76,71.88 143.76,74.93 144.78,75.95 153.42,75.95 v153.42,74.68 | v186.18,73.91 188.98,71.12 v188.98,70.87 | v193.04,70.87 199.39,77.22 v199.39,85.34 | v262.38,87.38 265.68,84.07 265.68,78.49 267.72,76.45 267.72,68.58 v267.21,68.07
  Bottom 0.254: v137.67,49.02 v139.7,49.02 | v153.42,74.68 153.67,74.93 185.17,74.93 v186.18,73.91 | v188.98,70.87 v193.04,70.87 | v199.39,85.34 201.42,87.38 v262.38,87.38 | v267.21,68.07 316.48,68.07 v318.52,66.04
GND  (via drill 0.61)
  Top 0.508: C7.1 340.11,14.73 336.55,18.29 336.55,30.73 335.53,31.75 E10.10 | C6.1 340.11,35.05 338.33,36.83 338.33,49.28 335.53,52.07 E9.10 335.53,54.61 338.33,57.4 338.33,72.39 340.11,74.17 C4.1 | E1.3 376.43,52.32 377.95,52.32 E1.4 378.97,52.32 380.49,52.32 E1.5 | E3.3 376.43,11.68 377.95,11.68 E3.4 378.97,11.68 380.49,11.68 E3.5 380.75,13.97 379.73,14.99 379.73,32 | E6.8 361.19,34.04 367.54,34.04 C2.1 | E2.3 376.43,32 377.95,32 E2.4 378.97,32 379.73,32 | 379.73,32 380.49,32 E2.5 | E4.8 360.43,72.39 359.41,71.37 359.41,55.63 360.43,54.61 E5.8 | 289.31,24.89 289.31,29.97 R19.1 | 289.31,24.89 289.31,23.37 R24.1 | 294.39,25.4 294.39,29.97 R20.1 | 294.39,25.4 294.39,24.89 | 294.39,24.89 294.39,23.37 R23.1 | 294.39,25.4 299.21,30.23 R18.1 | 294.39,24.89 289.31,24.89 | E14.8 282.19,31.75 283.21,30.73 283.21,16.26 282.19,15.24 E15.8 | C11.1 309.63,14.73 308.61,15.75 308.61,26.42 305.05,29.97 R17.1 305.31,30.73 309.12,34.54 C10.1 309.63,35.05 308.61,36.07 308.61,56.13 308.74,56.26 | 308.74,56.26 309.63,55.37 C9.1 | 308.74,56.26 308.61,56.39 308.61,73.15 309.63,74.17 C8.1 | E20.7 228.85,74.93 229.87,75.95 229.87,77.72 230.38,78.23 233.43,78.23 233.43,75.69 C16.1 | C12.1 261.37,72.9 259.08,70.61 259.08,57.66 261.37,55.37 C13.1 261.37,53.85 260.6,53.09 260.6,40.13 260.35,39.88 260.35,32.77 260.48,32.64 | v236.73,37.59 236.47,37.34 236.47,34.29 E18.1 235.97,31.75 234.95,30.73 234.95,13.72 | 260.48,32.64 261.37,33.53 C14.1 | 260.48,32.64 260.35,32.51 260.35,17.02 261.37,16 C15.1 | E23.7 229.11,13.72 232.92,13.72 C19.1 234.44,13.72 234.95,13.72 | 234.95,13.72 235.71,13.72 E19.1 236.47,13.97 236.47,17.27 v236.73,17.53
  Top 0.508: v197.61,16.26 197.61,20.07 197.87,20.32 E26.12 | R2.1 294.89,53.85 295.91,54.86 295.91,64.01 288.54,71.37 282.45,71.37 E12.8 | 205.36,56.52 205.49,56.64 205.49,71.12 209.04,74.68 210.06,74.68 C20.1 | 205.36,56.52 203.45,54.61 E24.7 203.2,52.07 v203.2,50.55 | v185.42,50.55 185.42,53.85 C24.1 | E17.15 238.51,59.69 236.47,57.66 236.47,54.61 E17.1 | E33.7 146.81,13.72 146.05,14.48 144.02,14.48 143.51,13.97 143.51,11.43 145.03,9.91 156.72,9.91 156.72,14.99 C30.1 157.73,16 158.75,17.02 158.75,22.86 157.73,23.88 157.73,33.53 C29.1 | 209.68,35.94 210.57,35.05 C22.1 | 209.68,35.94 209.55,36.07 209.55,52.83 210.57,53.85 C21.1 | v205.74,56.13 205.49,56.39 205.36,56.52 | C38.- 11.18,80.77 14.22,80.77 C39.- | J2.15 60.71,80.77 60.71,79.25 J2.16 60.96,78.23 60.96,41.15 J1.15 | J2.15 61.47,81.03 62.99,81.03 J2.13 64.01,81.03 65.53,81.03 J2.11 | J2.39 30.99,81.03 32.51,81.03 J2.37 33.53,81.03 35.05,81.03 J2.35 36.07,81.03 37.59,81.03 J2.33 38.61,81.03 40.13,81.03 J2.31 41.15,81.03 42.67,81.03 J2.29 43.69,81.03 45.21,81.03 J2.27 | J2.23 51.31,81.03 52.83,81.03 J2.21 53.85,81.03 55.37,81.03 J2.19 | J2.15 60.45,81.03 58.93,81.03 J2.17 | J1.39 30.99,40.39 32.51,40.39 J1.37 33.53,40.39 35.05,40.39 J1.35 36.07,40.39 37.59,40.39 J1.33 38.61,40.39 40.13,40.39 J1.31 41.15,40.39 42.67,40.39 J1.29 | J1.25 47.75,40.39 46.23,40.39 J1.27 | J1.19 55.37,40.39 53.85,40.39 J1.21 | 100.33,25.65 100.33,32.51 101.35,33.53 C35.1 101.85,35.05 102.87,36.07 102.87,52.83 101.85,53.85 C34.1 | 100.33,25.65 100.33,17.02 101.35,16 C36.1 | E35.8 121.67,31.75 120.65,30.73 120.65,16.26 121.67,15.24 E36.8
  Top 0.508: J4.8 122.17,72.39 123.19,71.37 123.19,56.9 122.17,55.88 122.17,54.61 E34.8 | v153.16,54.36 153.16,69.34 150.11,72.39 J3.8 | 100.33,25.65 79.25,25.65 67.31,37.59 67.31,39.12 66.29,40.13 J1.11 | E32.7 147.57,34.29 148.84,35.56 148.84,49.02 149.86,50.04 149.86,52.07 E31.8 | C23.1 210.57,14.73 209.55,15.75 209.55,35.81 209.68,35.94
  Bottom 0.508: C5.1 339.6,54.36 335.79,54.36 E9.10 334.77,54.36 334.01,55.12 319.28,55.12 318.77,54.61 318.77,51.56 311.66,51.56 308.86,54.36 | E11.10 335.79,13.72 339.6,13.72 C7.1 | E10.10 335.79,34.04 339.6,34.04 C6.1 | E8.7 328.17,74.68 339.6,74.68 C4.1 340.87,75.44 359.41,75.44 360.17,74.68 E4.8 | E5.8 361.19,54.36 367.54,54.36 C1.1 369.06,54.86 369.32,55.12 374.65,55.12 375.41,54.36 E1.3 | 384.81,51.56 385.57,52.32 E1.7 | 384.81,51.56 382.27,51.56 381.51,52.32 E1.5 | E7.8 361.19,13.72 367.54,13.72 C3.1 369.06,14.22 369.32,14.48 374.65,14.48 375.41,13.72 E3.3 | E3.7 385.57,11.68 384.81,10.92 382.27,10.92 381.51,11.68 E3.5 | E2.5 381.51,32 382.27,31.24 384.81,31.24 385.57,32 E2.7 385.83,34.29 384.81,34.29 384.81,51.56 | C2.1 369.06,34.54 369.32,34.8 374.65,34.8 375.41,34.04 E2.3 | R17.1 304.29,30.23 303.28,29.21 301.24,29.21 300.23,30.23 R18.1 | C11.1 309.12,13.72 306.07,13.72 305.31,12.95 R21.1 304.29,12.45 303.28,11.43 301.24,11.43 300.23,12.45 R22.1 299.21,12.95 298.2,13.97 282.45,13.97 E15.8 | 288.16,54.48 289.05,53.59 R1.1 | 288.16,54.48 288.04,54.61 282.7,54.61 282.45,54.36 E13.8 | 293.24,54.48 293.12,54.61 288.29,54.61 288.16,54.48 | 293.24,54.48 294.13,53.59 R2.1 | 293.24,54.48 293.37,54.61 298.2,54.61 299.21,53.59 R4.1 300.23,53.59 301.24,54.61 303.28,54.61 304.29,53.59 R3.1 305.31,53.59 306.07,54.36 308.86,54.36 | 308.86,54.36 309.12,54.36 C9.1 | E17.8 254.51,54.36 260.86,54.36 C13.1 | E12.8 281.43,73.41 279.91,74.93 262.89,74.93 262.13,74.17 C12.1 260.86,73.41 251.97,73.41 E16.7 250.95,74.68 250.19,75.44 234.7,75.44 234.44,75.18 C16.1 | E19.8 254.51,13.72 255.78,14.99 260.86,14.99 C15.1
  Bottom 0.508: C14.1 260.86,34.04 254.51,34.04 E18.8 253.49,32 252.73,31.24 237.49,31.24 236.73,32 E18.1 235.71,34.04 234.44,34.04 C18.1 232.92,34.04 229.11,34.04 E22.7 | v236.73,37.59 238.51,39.37 E18.15 | v236.73,17.53 236.98,17.53 238.51,19.05 E19.15 | E30.7 175.77,14.99 184.66,14.99 C26.1 185.93,15.75 197.1,15.75 v197.61,16.26 197.87,16 208.28,16 210.06,14.22 C23.1 211.33,14.48 227.33,14.48 228.09,13.72 E23.7 | E28.8 178.31,54.36 184.66,54.36 C24.1 | v185.42,50.55 185.67,50.8 202.95,50.8 v203.2,50.55 | E17.1 235.71,54.36 234.44,54.36 C17.1 232.92,54.36 229.11,54.36 E21.7 228.09,54.36 227.33,55.12 211.84,55.12 211.58,54.86 C21.1 210.06,54.86 207.01,54.86 v205.74,56.13 | C22.1 210.06,34.04 203.71,34.04 E25.7 202.69,34.04 201.93,34.8 195.33,34.8 | E32.7 147.83,34.04 156.72,34.04 C29.1 157.99,34.8 176.53,34.8 177.29,34.04 E29.8 178.31,34.04 184.66,34.04 C25.1 185.93,34.8 192.79,34.8 | 195.33,34.8 192.79,34.8 | J2.27 46.23,81.03 47.75,81.03 J2.25 48.77,81.03 50.29,81.03 J2.23 | J2.17 57.91,81.03 56.39,81.03 J2.19 | C39.- 16.26,81.79 17.27,82.8 28.7,82.8 29.97,81.53 J2.39 | 6.86,24.13 5.84,23.11 R27.2 | 6.86,24.13 10.92,24.13 11.94,25.15 R30.2 | 6.86,24.13 6.86,38.86 GND.1 9.4,41.4 10.16,42.16 28.7,42.16 29.97,40.89 J1.39 | J1.27 45.21,40.39 43.69,40.39 J1.29 | J1.25 48.77,40.39 50.29,40.39 J1.23 51.31,40.39 52.83,40.39 J1.21 | J1.19 56.39,40.39 57.91,40.39 J1.17 58.93,40.39 60.45,40.39 J1.15 61.47,40.39 62.99,40.39 J1.13 64.01,40.39 65.53,40.39 J1.11 | E35.8 122.43,34.04 128.78,34.04 C32.1 | C33.1 128.78,13.72 122.43,13.72 E36.8 121.41,14.99 120.65,15.75 102.11,15.75 C36.1
  Bottom 0.508: J3.8 150.37,73.41 156.72,73.41 C27.1 157.99,74.17 173.99,74.17 174.75,73.41 E27.7 | C28.1 156.72,54.36 v153.16,54.36 150.37,54.36 E31.8 149.35,54.36 148.59,55.12 130.05,55.12 C31.1 128.78,54.36 122.43,54.36 E34.8 121.41,54.36 119.89,55.88 103.38,55.88 102.36,54.86 C34.1 | 192.79,34.8 192.79,34.29 E25.3 | 195.33,34.8 195.33,34.29 E25.4
  pour Top (isolate 0.254): 0,0 0,93.98 393.7,93.98 393.7,0
IND1\  (via drill 0.61)
  Top 0.254: v86.36,53.34 71.37,68.33 71.37,78.23 J2.8 | v139.19,29.72 138.68,29.21 138.68,19.05 140.72,17.02 140.72,4.32 161.54,4.32 169.16,11.94 169.16,15.24 171.2,17.27 171.2,29.97 171.45,30.23 171.45,57.4 174.75,57.4 175.51,56.64 175.51,54.61 E28.7 | v112.27,30.23 110.24,32.26 110.24,50.8 109.47,51.56 109.47,52.07 E34.3
  Bottom 0.254: v86.36,53.34 102.87,53.34 102.87,54.36 103.63,55.12 107.95,55.12 108.71,54.36 E34.3 | v139.19,29.72 138.68,30.23 v112.27,30.23
IND2\  (via drill 0.61)
  Top 0.254: v93.22,49.53 76.45,66.29 76.45,78.23 J2.4
  Bottom 0.254: v93.22,49.53 119.13,49.53 119.13,51.31 118.36,52.07 118.36,54.1 117.35,55.12 115.57,55.12 114.81,54.36 E34.5
INIT\  (via drill 0.61)
  Top 0.254: v143.76,57.66 145.8,59.69 145.8,75.44 147.83,75.44 148.84,74.42 148.84,62.99 149.61,62.23 E31.9 | v38.35,71.63 38.35,78.23 J2.34
  Bottom 0.254: v143.76,57.66 117.86,57.66 115.32,60.2 115.32,63.5 82.04,63.5 80.01,65.53 44.45,65.53 v38.35,71.63
KEY-F\  (via drill 0.61)
  Top 0.254: 195.33,19.81 195.33,20.32 E26.13 | 195.33,19.81 195.33,15.24 E26.4 | v130.56,72.39 v130.56,67.31 | v169.93,67.56 170.18,67.82 170.18,71.12 E27.5 | 195.33,19.81 186.69,19.81 186.69,22.35 182.63,26.42 182.63,56.13 183.13,56.64 183.13,63.75 181.1,65.79 v181.1,67.06
  Bottom 0.254: v130.56,72.39 127.51,75.44 110.49,75.44 109.73,74.68 J4.3 | v130.56,67.31 151.64,67.31 151.89,67.56 v169.93,67.56 170.18,67.31 170.43,67.06 v181.1,67.06
KEYCNTL\  (via drill 0.61)
  Top 0.254: v137.16,68.83 137.16,64.52 139.45,62.23 E31.13 | v68.58,68.58 68.58,78.23 J2.10
  Bottom 0.254: v137.16,68.83 136.65,68.33 131.57,68.33 131.06,68.83 118.87,68.83 117.09,67.06 83.06,67.06 82.55,67.56 80.01,67.56 78.99,68.58 v68.58,68.58
KEYSTB  (via drill 0.61)
  Top 0.254: v191.26,55.37 191.52,55.63 191.52,75.18 v191.01,75.69
  Bottom 0.254: v191.26,55.37 189.48,55.37 188.47,54.36 E24.1 | J4.2 107.19,74.68 108.71,76.2 190.5,76.2 v191.01,75.69 191.26,75.95 192.02,75.95 192.28,76.2 293.88,76.2 298.2,71.88 321.31,71.88 322.07,72.64 E8.5
KEYSTB\  (via drill 0.61)
  Top 0.254: v242.32,50.04 242.32,78.74 243.59,80.01 E16.11 | v140.72,51.56 140.72,22.35 139.95,21.59 E33.11
  Bottom 0.254: E33.11 140.21,19.3 140.97,18.54 143.51,18.54 144.27,19.3 E33.9 | 189.23,51.56 v140.72,51.56 133.35,51.56 132.59,52.32 E31.1 | 189.23,51.56 189.99,52.32 E24.2 | 214.63,51.56 215.39,52.32 E21.2 | 214.63,51.56 189.23,51.56 | v242.32,50.04 229.36,50.04 227.84,51.56 214.63,51.56
KFUN0\  (via drill 0.61)
  Top 0.254: E3.2 372.87,11.68 371.35,11.68 E3.1 370.33,11.68 370.33,8.89 294.39,8.89 292.61,10.67 272.03,10.67 268.73,7.37 268.73,4.83 197.1,4.83 192.02,9.91 192.02,11.43 190.75,12.7 E26.2 190.25,15.24 190.25,15.75 188.21,15.75 180.09,23.88 180.09,26.92 181.1,27.94 v181.1,59.18 | v140.21,65.79 140.21,69.6 137.41,72.39 J3.3 | v168.91,59.44 v168.91,65.53
  Bottom 0.254: v140.21,65.79 140.72,66.29 167.13,66.29 167.39,66.55 167.89,66.55 v168.91,65.53 | v168.91,59.44 169.16,59.18 v181.1,59.18
KFUN1\  (via drill 0.61)
  Top 0.254: v193.04,10.16 193.04,12.7 E26.3 | v131.06,8.38 126.24,13.21 126.24,78.49 129.29,81.53 130.56,81.53 130.56,78.74 134.37,74.93 J3.2 | v362.71,9.91 362.71,23.88 370.59,31.75 E2.1
  Bottom 0.254: E2.1 371.35,32 372.87,32 E2.2 | v131.06,8.38 171.7,8.38 171.96,8.13 173.23,8.13 173.74,8.64 175.51,8.64 177.55,10.67 192.53,10.67 v193.04,10.16 193.29,9.91 193.55,9.65 203.45,9.65 203.96,10.16 213.11,10.16 214.38,8.89 266.7,8.89 268.48,10.67 274.83,10.67 275.08,10.41 362.2,10.41 v362.71,9.91
KFUN2\  (via drill 0.61)
  Top 0.254: E1.2 372.87,52.32 371.35,52.32 E1.1 370.59,52.07 369.57,51.05 369.57,33.78 v362.97,27.18 | v244.35,25.4 242.32,23.37 242.32,9.4 240.54,7.62 204.22,7.62 | 204.22,7.62 202.95,7.62 202.95,9.65 200.91,11.68 200.91,12.7 E26.6 | v131.32,38.61 132.33,38.61 133.1,39.37 133.1,62.23 131.83,63.5 131.83,72.39 J3.1 | v127.76,36.83 127.51,36.58 127.51,22.86 v129.54,20.83 | v183.39,19.05 186.94,15.49 186.94,12.7 v192.79,6.86 | 204.22,7.62 v204.22,6.86
  Bottom 0.254: v362.97,27.18 361.19,25.4 v244.35,25.4 | v131.32,38.61 131.32,39.12 130.81,39.62 130.81,40.64 129.03,40.64 127.25,38.86 127.25,36.83 v127.76,36.83 | v129.54,20.83 131.06,19.3 131.06,18.03 152.15,18.03 153.67,19.56 156.46,19.56 156.97,19.05 164.34,19.05 164.85,19.56 173.23,19.56 173.74,19.05 v183.39,19.05 | v204.22,6.86 v192.79,6.86
LAENAB\  (via drill 0.61)
  Top 0.254: v212.85,9.14 215.39,11.68 E23.2 | v189.23,9.14 182.12,16.26 v182.12,17.53 | v80.01,17.53 59.69,37.85 59.69,67.56 53.59,73.66 53.59,78.23 J2.22
  Bottom 0.254: v189.23,9.14 v212.85,9.14 | v182.12,17.53 181.1,18.54 166.37,18.54 165.35,17.53 v80.01,17.53
LDSR  (via drill 0.61)
  Top 0.254: E7.9 360.43,21.59 359.66,22.35 359.66,38.61 360.43,39.37 E6.9 360.93,41.91 361.7,42.67 361.7,62.99 | v193.55,89.92 187.96,84.33 187.96,77.72 175.26,77.72 173.74,79.25 173.74,82.04 171.96,83.82 171.96,91.19 154.69,91.19 148.84,85.34 148.84,79.5 140.72,79.5 136.14,74.93 136.14,58.42 135.64,57.91 135.64,22.35 134.87,21.59 E33.13 | v360.43,76.2 361.7,74.93 361.7,62.99 | 361.7,62.99 360.93,62.23 E5.9
  Bottom 0.254: v193.55,89.92 194.56,90.93 264.41,90.93 272.03,83.31 277.11,83.31 277.88,84.07 334.52,84.07 342.39,76.2 v360.43,76.2
MAEN\  (via drill 0.61)
  Top 0.254: v235.2,88.39 235.2,40.89 233.43,40.89 232.41,39.88 232.41,25.15 228.85,21.59 E23.8 | v180.59,78.74 v189.74,87.88 | v161.54,78.23 161.04,78.74 v161.04,86.11 | v149.1,87.63 144.02,92.71 99.57,92.71 99.57,85.34 90.68,76.45 81.53,76.45 v81.53,77.47
  Bottom 0.254: v235.2,88.39 234.7,87.88 v189.74,87.88 | v180.59,78.74 180.09,78.23 v161.54,78.23 | v161.04,86.11 159.51,87.63 v149.1,87.63 | v81.53,77.47 78.99,80.01 42.16,80.01 41.15,78.99 J2.32
MALC\  (via drill 0.61)
  Top 0.254: v159,69.85 159,70.61 163.58,70.61 164.59,69.6 164.59,64.52 166.12,62.99 166.12,58.42 169.16,58.42 169.67,58.93 171.2,58.93 172.21,59.94 E28.11 | v135.13,70.36 135.64,70.87 135.64,75.44 131.06,80.01 131.06,82.55 130.56,83.06 120.4,83.06 120.4,80.01 v117.6,77.22 | v37.34,75.44 35.81,76.96 35.81,78.23 J2.36
  Bottom 0.254: v159,69.85 158.5,69.34 152.65,69.34 152.4,69.6 145.29,69.6 145.03,69.34 138.94,69.34 137.92,70.36 v135.13,70.36 | v117.6,77.22 117.09,76.71 85.85,76.71 84.58,75.44 v37.34,75.44
MCLOCK\  (via drill 0.61)
  Top 0.254: v127.25,70.36 126.75,69.85 126.75,17.78 130.05,17.78 134.11,13.72 E33.2
  Bottom 0.254: v127.25,70.36 126.75,69.85 107.44,69.85 104.65,72.64 J4.1
MD\  (via drill 0.61)
  Top 0.254: v120.4,66.8 120.4,55.37 119.63,54.61 E34.7 | v59.94,68.58 58.67,69.85 58.67,78.23 J2.18
  Bottom 0.254: v120.4,66.8 119.89,66.29 117.86,66.29 117.6,66.04 82.04,66.04 81.53,66.55 61.98,66.55 v59.94,68.58
MEMSTART\  (via drill 0.61)
  Top 0.254: v194.56,23.37 194.06,23.88 194.06,37.34 191.52,39.88 191.52,43.69 188.98,46.23 188.98,65.53 v183.64,70.87 | v179.58,70.87 171.2,79.25 171.2,83.06 166.88,87.38 166.88,87.88 164.08,90.68 154.94,90.68 v154.94,86.61 | v141.22,85.6 138.68,85.6 v137.67,84.58 | v88.9,79.5 85.34,83.06 49.53,83.06 49.53,80.26 48.51,79.25 J2.26
  Bottom 0.254: v194.56,23.37 215.9,23.37 217.93,21.34 E23.12 | v179.58,70.87 v183.64,70.87 | v154.94,86.61 153.92,85.6 v141.22,85.6 | v137.67,84.58 137.16,84.07 107.19,84.07 105.16,82.04 105.16,79.5 v88.9,79.5
MH0  (via drill 0.61)
  Top 0.254: 222.5,76.71 225.81,80.01 E20.9 | 222.5,76.71 222,76.2 222,42.67 221.23,41.91 E22.11 | v268.48,77.98 267.72,78.74 267.72,83.82 261.62,89.92 222.5,89.92 222.5,76.71
  Bottom 0.254: v268.48,77.98 312.17,77.98 314.45,80.26 E8.13
MH0\  (via drill 0.61)
  Top 0.254: E21.9 226.31,62.23 227.58,63.5 v227.58,68.58 227.58,79.25 228.35,80.01 E20.8 | v312.67,69.6 312.67,70.36 314.71,72.39 E8.2
  Bottom 0.254: E8.2 315.47,74.68 319.79,78.99 323.34,78.99 324.61,80.26 E8.9 | E20.12 218.95,80.26 219.71,79.5 227.33,79.5 228.09,80.26 E20.8 | v312.67,69.6 312.17,69.09 245.62,69.09 245.11,68.58 v227.58,68.58
MPXA  (via drill 0.61)
  Top 0.254: 240.28,22.35 241.05,21.59 E19.14 | 240.28,22.35 240.28,38.61 | 240.28,38.61 241.05,39.37 E18.14 | 240.28,38.61 240.28,58.93 241.05,59.69 E17.14 | v100.58,77.72 99.57,76.71 99.57,26.92 v99.31,26.67 | v121.92,26.16 123.7,24.38 123.7,11.94 v131.83,3.81 | v134.62,3.81 135.13,3.3 172.97,3.3 v172.97,5.33 | v171.7,6.6 171.45,6.86 171.45,16.76 171.7,17.02 171.7,23.37 v172.21,23.88 | v191.52,23.37 193.04,24.89 v193.04,26.67 | v223.52,24.64 225.04,23.11 225.04,10.16 225.81,9.4 240.28,9.4 240.28,22.35
  Bottom 0.254: v100.58,77.72 106.17,77.72 108.71,80.26 J4.14 | v99.31,26.67 99.82,26.16 v121.92,26.16 | v134.62,3.81 v131.83,3.81 | v171.7,6.6 v172.97,5.33 | v172.21,23.88 172.72,23.37 v191.52,23.37 | v193.04,26.67 195.33,28.96 205.74,28.96 206.5,28.19 207.26,28.19 207.52,28.45 214.38,28.45 218.19,24.64 v223.52,24.64
MPXB  (via drill 0.61)
  Top 0.254: 237.74,30.99 237.74,14.73 238.51,13.97 E19.2 | 237.74,30.99 238.51,31.75 E18.2 | 237.74,30.99 237.74,51.31 238.51,52.07 E17.2 239.01,54.61 239.78,55.37 v239.78,86.11 | v118.11,88.14 112.27,82.3 J4.13 | v178.82,84.33 179.32,83.82 v179.32,79.25 | v200.41,79.25 v207.26,86.11
  Bottom 0.254: v118.11,88.14 118.62,88.65 145.54,88.65 146.56,89.66 161.29,89.66 162.31,88.65 174.24,88.65 178.56,84.33 v178.82,84.33 | v179.32,79.25 179.83,79.76 199.9,79.76 v200.41,79.25 | v207.26,86.11 v239.78,86.11
MSIRDIS\  (via drill 0.61)
  Top 0.254: v143.26,68.33 143.26,63.5 144.53,62.23 E31.11 | v78.74,67.56 78.74,78.23 J2.2
  Bottom 0.254: v143.26,68.33 142.75,67.82 131.32,67.82 130.81,68.33 119.13,68.33 117.35,66.55 82.8,66.55 82.3,67.06 79.25,67.06 v78.74,67.56
N$1
  Top 0.254: E10.6 325.37,31.75 326.64,30.48 326.64,28.7 334.26,21.08 334.26,18.29 341.63,10.92 349,10.92 349,35.56 352.81,39.37 E6.12
  Bottom 0.254: E2.12 375.41,41.66 374.65,42.42 364.74,42.42 361.19,38.86 354.33,38.86 353.57,39.62 E6.12
N$2
  Top 0.254: E9.6 325.37,54.61 326.64,55.88 326.64,68.07 339.85,81.28 341.88,81.28 341.88,79.5 346.96,74.42 346.96,68.07 352.81,62.23 E5.12
  Bottom 0.254: E1.12 375.41,61.98 374.65,62.74 364.74,62.74 361.19,59.18 354.33,59.18 353.57,59.94 E5.12
N$3
  Bottom 0.254: E9.2 315.47,54.36 316.99,55.88 343.92,55.88 344.68,55.12 349.25,55.12 350.01,54.36 E5.4 351.03,54.36 352.55,55.88 376.43,55.88 380.49,59.94 E1.10
N$4
  Bottom 0.254: 351.79,51.56 321.31,51.56 320.55,52.32 E9.4 | 351.79,51.56 352.55,52.32 E5.5 | 351.79,51.56 376.94,51.56 376.94,54.1 377.95,55.12 382.02,55.12 382.02,62.23 381.51,62.74 379.73,62.74 378.97,61.98 E1.11
N$5
  Bottom 0.254: 349.25,31.24 316.23,31.24 315.47,32 E10.2 | 349.25,31.24 350.01,32 E6.4 | 349.25,31.24 361.19,31.24 365.51,35.56 376.43,35.56 380.49,39.62 E2.10
N$6
  Bottom 0.254: E10.4 320.55,34.04 322.07,35.56 351.03,35.56 352.55,34.04 E6.5 353.57,34.04 355.6,36.07 374.4,36.07 377.95,39.62 E2.11
N$7
  Top 0.254: E11.6 325.63,11.68 327.41,9.91 352.04,9.91 352.04,18.29 352.81,19.05 E7.12
  Bottom 0.254: E3.12 375.41,21.34 374.65,22.1 364.74,22.1 361.19,18.54 354.33,18.54 353.57,19.3 E7.12
N$8
  Bottom 0.254: 349.25,10.92 316.23,10.92 315.47,11.68 E11.2 | 349.25,10.92 350.01,11.68 E7.4 | 349.25,10.92 376.94,10.92 376.94,13.46 377.95,14.48 380.75,14.48 380.75,19.05 E3.10
N$9
  Bottom 0.254: 351.03,15.24 322.07,15.24 320.55,13.72 E11.4 | 351.03,15.24 352.55,13.72 E7.5 | 351.03,15.24 373.89,15.24 377.95,19.3 E3.11
N$10
  Bottom 0.254: E19.3 241.81,11.68 242.57,10.92 259.08,10.92 263.14,14.99 263.14,15.75 265.43,15.75 266.19,14.99 E15.2
N$11  (via drill 0.61)
  Top 0.254: v246.89,9.91 246.89,11.18 246.63,11.43 E19.5
  Bottom 0.254: v246.89,9.91 247.4,10.41 267.46,10.41 268.73,11.68 279.4,11.68 280.42,12.7 280.42,15.75 275.59,15.75 274.83,14.99 E15.5
N$12  (via drill 0.61)
  Top 0.254: v252.98,14.48 260.6,14.48 v262.89,12.19
  Bottom 0.254: v252.98,14.48 245.11,14.48 244.35,13.72 E19.4 | v262.89,12.19 278.13,12.19 278.89,12.95 E15.7
N$13  (via drill 0.61)
  Top 0.254: v252.98,24.38 252.98,17.78 249.17,13.97 E19.6
  Bottom 0.254: v252.98,24.38 253.49,23.88 274.32,23.88 275.84,22.35 275.84,19.81 278.13,19.81 278.89,20.57 E15.10
N$14
  Bottom 0.254: E19.13 244.35,21.34 246.38,23.37 273.05,23.37 273.81,22.61 E15.12
N$15  (via drill 0.61)
  Top 0.254: v266.7,18.54 266.7,20.32 E15.15
  Bottom 0.254: v266.7,18.54 250.19,18.54 249.43,19.3 E19.11
N$16  (via drill 0.61)
  Top 0.254: v259.59,52.58 259.59,34.54 246.63,21.59 E19.12
  Bottom 0.254: v259.59,52.58 260.35,53.34 262.13,53.34 263.14,54.36 263.14,55.12 265.43,55.12 266.19,54.36 E13.2
N$17  (via drill 0.61)
  Top 0.254: v272.8,19.81 273.3,20.32 273.3,37.34 275.34,39.37 275.34,43.69 273.81,45.21 273.81,52.32 E13.5
  Bottom 0.254: v272.8,19.81 266.7,19.81 265.94,19.05 261.11,19.05 258.06,22.1 252.73,22.1 251.97,21.34 E19.10
N$18
  Top 0.254: E18.3 241.55,31.75 245.36,27.94 245.36,16 247.9,13.46 247.9,8.64 249.68,6.86 267.72,6.86 267.72,7.87 272.03,12.19 280.42,12.19 280.42,51.31 279.65,52.07 E13.7
N$19  (via drill 0.61)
